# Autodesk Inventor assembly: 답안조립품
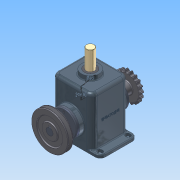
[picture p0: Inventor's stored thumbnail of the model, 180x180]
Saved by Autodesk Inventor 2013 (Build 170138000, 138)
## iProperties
Created: 2015-03
Part Number: 답안조립품
Document SubType Name: Assembly
Designer: Administrator
Mass: 8579.28 g
Surface Area: 4386.42 cm^2
Volume: 1982.54 cm^3
Density: 4.32742 g/cm^3
Author: Administrator
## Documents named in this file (15)
- C:\Documents and Settings\Administrator\바탕 화면\350305V1023\답안조립품.iam
- C:\Documents and Settings\Administrator\바탕 화면\350305V1023\본체.ipt
- C:\Documents and Settings\Administrator\바탕 화면\350305V1023\커버.ipt
- C:\Documents and Settings\Administrator\바탕 화면\350305V1023\베어링 6205.ipt
- C:\Documents and Settings\Administrator\바탕 화면\350305V1023\M4x0.5.ipt
- C:\Documents and Settings\Administrator\바탕 화면\350305V1023\오일실.ipt
- C:\Documents and Settings\Administrator\바탕 화면\350305V1023\편심축.ipt
- C:\Documents and Settings\Administrator\바탕 화면\350305V1023\키 8x8.ipt
- C:\Documents and Settings\Administrator\바탕 화면\350305V1023\V-벨트풀리.ipt
- C:\Documents and Settings\Administrator\바탕 화면\350305V1023\체인 스프로킷.ipt
- C:\Documents and Settings\Administrator\바탕 화면\350305V1023\멈춤링.ipt
- C:\Documents and Settings\Administrator\바탕 화면\350305V1023\멈춤나사 M5x0.5.ipt
- C:\Documents and Settings\Administrator\바탕 화면\350305V1023\부시.ipt
- C:\Documents and Settings\Administrator\바탕 화면\350305V1023\슬라이드.ipt
- C:\Documents and Settings\Administrator\바탕 화면\350305V1023\7-가변스프링.ipt
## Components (9 placed, 4 different names)
1. V-벨트풀리:1 — 각도:3, 플러쉬:1
2. 5-체인 스프로킷:1 — 각도:4, 플러쉬:2
3. 7-가변스프링:1
4. M4x0.5:2
5. M4x0.5:3
6. M4x0.5:4
7. M4x0.5:1
8. M4x0.5:5
9. M4x0.5:6
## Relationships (4: Angle 2, Flush 2)
- 각도:3 [Angle]: V-벨트풀리:1
- 플러쉬:1 [Flush]: V-벨트풀리:1
- 각도:4 [Angle]: 5-체인 스프로킷:1
- 플러쉬:2 [Flush]: 5-체인 스프로킷:1
